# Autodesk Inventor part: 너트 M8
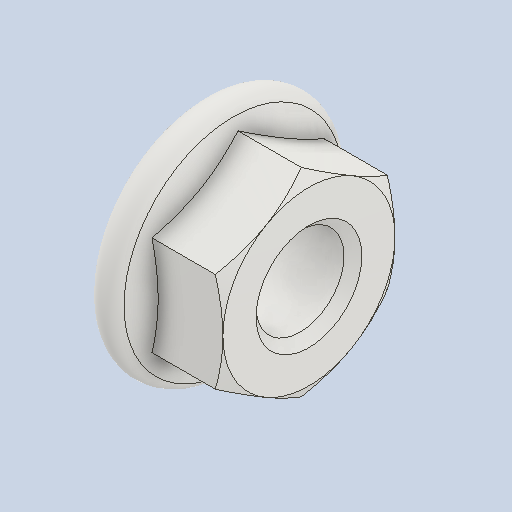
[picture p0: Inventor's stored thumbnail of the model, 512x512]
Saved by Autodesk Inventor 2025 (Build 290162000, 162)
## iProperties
Created: 2024-07
Part Number: 너트 M8
Material: 스테인리스강
Description: 플랜지붙이 6각 너트 - 일반 스레드
Document SubType Name: Modeling
Designer: samsung
Density: 8 g/cm^3
Appearance: 기본값
Author: jhkim
Sending System: Autodesk Inventor 2025
Preprocessor: ST-DEVELOPER v20
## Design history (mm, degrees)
feature "Solid1"
node "솔리드1"
